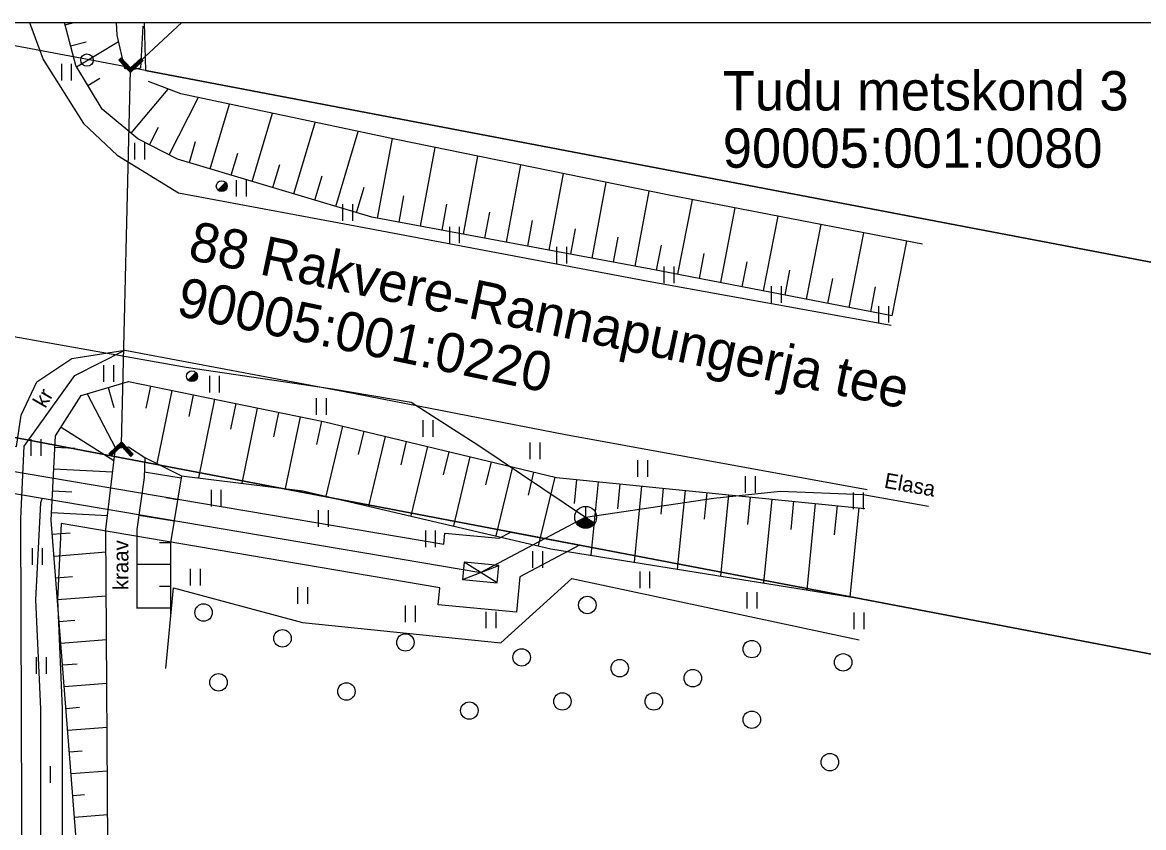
# Model space of a CAD drawing. Extents: x 657488 to 657645, y 6569018 to 6569240.
# Drawn here: x 657566.2 to 657617.6, y 6569166 to 6569202.9 of the extents above; entities that cross this region are included whole.
import ezdxf

# ---------------------------------------------------------------- set-up
doc = ezdxf.new("R2010")
doc.units = 0
for name, color, linetype in [('HALJASTUS', 7, 'Continuous'), ('KASUTUSALA', 7, 'Continuous'), ('PIIR', 7, 'Continuous'), ('PIIRIMLEITUD', 7, 'Continuous'), ('POST', 7, 'Continuous'), ('PR_SIDE', 7, 'Continuous'), ('RELJEEF', 7, 'Continuous'), ('SIKAEV', 7, 'Continuous'), ('SITRASS', 7, 'Continuous'), ('TEE', 7, 'Continuous'), ('TRUUP', 7, 'Continuous'), ('VEEKOGU', 7, 'Continuous'), ('VORMISTUS', 7, 'Continuous')]:
    doc.layers.add(name, color=color, linetype=linetype)

msp = doc.modelspace()

# ---------------------------------------------------------------- linework, layer by layer
at = {"layer": 'HALJASTUS'}
for p, q in [((657567.968, 6569200.963), (657567.968, 6569200.201)), ((657568.423, 6569200.963), (657568.423, 6569200.201)), ((657571.325, 6569197.337), (657571.325, 6569196.576)), ((657571.78, 6569197.337), (657571.78, 6569196.576)), ((657575.983, 6569195.634), (657575.983, 6569194.873)), ((657576.438, 6569195.634), (657576.438, 6569194.873)), ((657580.858, 6569194.531), (657580.858, 6569193.769)), ((657581.313, 6569194.531), (657581.313, 6569193.769)), ((657585.75, 6569193.495), (657585.75, 6569192.734)), ((657586.205, 6569193.495), (657586.205, 6569192.734)), ((657590.665, 6569192.576), (657590.665, 6569191.815)), ((657591.12, 6569192.576), (657591.12, 6569191.815)), ((657595.582, 6569191.67), (657595.582, 6569190.909)), ((657596.037, 6569191.67), (657596.037, 6569190.909)), ((657600.499, 6569190.765), (657600.499, 6569190.003)), ((657600.954, 6569190.765), (657600.954, 6569190.003)), ((657605.416, 6569189.859), (657605.416, 6569189.098)), ((657605.871, 6569189.859), (657605.871, 6569189.098)), ((657569.902, 6569187.152), (657569.902, 6569186.391)), ((657570.357, 6569187.152), (657570.357, 6569186.391)), ((657574.749, 6569186.655), (657574.749, 6569185.894)), ((657575.204, 6569186.655), (657575.204, 6569185.894)), ((657579.644, 6569185.638), (657579.644, 6569184.877)), ((657580.099, 6569185.638), (657580.099, 6569184.877)), ((657584.54, 6569184.621), (657584.54, 6569183.859)), ((657584.995, 6569184.621), (657584.995, 6569183.859)), ((657566.567, 6569183.759), (657566.567, 6569182.998)), ((657567.022, 6569183.759), (657567.022, 6569182.998)), ((657589.435, 6569183.604), (657589.435, 6569182.842)), ((657589.89, 6569183.604), (657589.89, 6569182.842)), ((657594.368, 6569182.796), (657594.368, 6569182.035)), ((657594.823, 6569182.796), (657594.823, 6569182.035)), ((657599.313, 6569182.056), (657599.313, 6569181.295)), ((657599.768, 6569182.056), (657599.768, 6569181.295)), ((657574.825, 6569181.436), (657574.825, 6569180.675)), ((657575.28, 6569181.436), (657575.28, 6569180.675)), ((657604.258, 6569181.316), (657604.258, 6569180.555)), ((657604.713, 6569181.316), (657604.713, 6569180.555)), ((657579.737, 6569180.5), (657579.737, 6569179.739)), ((657580.192, 6569180.5), (657580.192, 6569179.739)), ((657584.648, 6569179.564), (657584.648, 6569178.803)), ((657585.104, 6569179.564), (657585.104, 6569178.803)), ((657566.63, 6569178.761), (657566.63, 6569177.999)), ((657567.085, 6569178.761), (657567.085, 6569177.999)), ((657589.56, 6569178.628), (657589.56, 6569177.867)), ((657590.015, 6569178.628), (657590.015, 6569177.867)), ((657573.868, 6569177.812), (657573.868, 6569177.051)), ((657574.323, 6569177.812), (657574.323, 6569177.051)), ((657594.471, 6569177.69), (657594.471, 6569176.928)), ((657594.926, 6569177.69), (657594.926, 6569176.928)), ((657578.796, 6569176.97), (657578.796, 6569176.209)), ((657579.251, 6569176.97), (657579.251, 6569176.209)), ((657599.382, 6569176.751), (657599.382, 6569175.99)), ((657599.837, 6569176.751), (657599.837, 6569175.99)), ((657583.725, 6569176.127), (657583.725, 6569175.366)), ((657584.18, 6569176.127), (657584.18, 6569175.366)), ((657587.428, 6569175.85), (657587.428, 6569175.089)), ((657587.883, 6569175.85), (657587.883, 6569175.089)), ((657604.293, 6569175.812), (657604.293, 6569175.051)), ((657604.748, 6569175.812), (657604.748, 6569175.051)), ((657566.818, 6569173.764), (657566.818, 6569173.003)), ((657567.273, 6569173.764), (657567.273, 6569173.003)), ((657567.006, 6569168.768), (657567.006, 6569168.007)), ((657567.461, 6569168.768), (657567.461, 6569168.007))]:
    msp.add_line(p, q, dxfattribs=at)
msp.add_lwpolyline([(657572.749, 6569173.24), (657573.113, 6569176.938), (657579.023, 6569175.362), (657588.106, 6569174.428), (657591.366, 6569177.373), (657604.523, 6569174.557)], dxfattribs=at)
for centre in [(657592.072, 6569176.155), (657574.484, 6569175.812), (657578.1, 6569174.631), (657583.735, 6569174.441), (657599.61, 6569174.136), (657589.064, 6569173.755), (657603.797, 6569173.527), (657593.557, 6569173.26), (657596.907, 6569172.803), (657575.169, 6569172.613), (657581.032, 6569172.194), (657586.666, 6569171.318), (657590.93, 6569171.737), (657595.118, 6569171.737), (657599.61, 6569170.899), (657603.188, 6569168.956)]:
    msp.add_circle(centre, 0.4, dxfattribs=at)
at = {"layer": 'KASUTUSALA'}
msp.add_lwpolyline([(657547.908, 6569185.316), (657566.447, 6569182.172), (657567.352, 6569182.019), (657585.5, 6569178.941), (657585.549, 6569179.455), (657588.033, 6569179.219), (657588.559, 6569179.496), (657591.709, 6569178.895), (657588.975, 6569177.455), (657588.82, 6569175.829), (657585.236, 6569176.17), (657585.31, 6569176.945), (657567.959, 6569179.887), (657567.787, 6569176.392), (657568.004, 6569171.419), (657568.004, 6569151.046), (657568.454, 6569143.738), (657568.454, 6569131.107), (657569.487, 6569109.777)], dxfattribs=at)
at = {"layer": 'PIIR'}
for p, q in [((657628.561, 6569171.87), (657504.811, 6569195.461)), ((657504.811, 6569195.461), (657628.561, 6569171.87))]:
    msp.add_line(p, q, dxfattribs=at)
for points in [[(657628.561, 6569189.835), (657571.83, 6569200.65), (657569.16, 6569201.16), (657560.132, 6569202.856)], [(657571.761, 6569202.856), (657571.83, 6569200.65), (657569.16, 6569201.16), (657560.132, 6569202.856)], [(657571.761, 6569202.856), (657571.83, 6569200.65), (657628.561, 6569189.835)]]:
    msp.add_lwpolyline(points, dxfattribs=at)
at = {"layer": 'PIIRIMLEITUD'}
msp.add_circle((657569.14, 6569201.13), 0.285, dxfattribs=at)
at = {"layer": 'POST'}
for p, q in [((657575.14, 6569195.174), (657575.494, 6569195.527)), ((657573.777, 6569186.466), (657574.131, 6569186.819))]:
    msp.add_line(p, q, dxfattribs=at)
for centre in [(657575.317, 6569195.351), (657573.954, 6569186.643)]:
    msp.add_circle(centre, 0.25, dxfattribs=at)
for centre, radius, start, end in [((657575.317, 6569195.351), 0.225, 224.8541, 45.0356), ((657575.317, 6569195.351), 0.2, 224.8427, 45.047), ((657575.317, 6569195.351), 0.175, 224.8281, 45.0616), ((657575.317, 6569195.351), 0.15, 224.8087, 45.081), ((657575.317, 6569195.351), 0.125, 224.7814, 45.1083), ((657575.317, 6569195.351), 0.1, 224.7406, 45.1491), ((657575.317, 6569195.351), 0.075, 224.6725, 45.2172), ((657575.317, 6569195.351), 0.05, 224.5363, 45.3534), ((657575.317, 6569195.351), 0.025, 224.1278, 45.7619), ((657573.954, 6569186.643), 0.225, 224.8541, 45.0356), ((657573.954, 6569186.643), 0.2, 224.8427, 45.047), ((657573.954, 6569186.643), 0.175, 224.8281, 45.0616), ((657573.954, 6569186.643), 0.15, 224.8087, 45.081), ((657573.954, 6569186.643), 0.125, 224.7814, 45.1083), ((657573.954, 6569186.643), 0.1, 224.7406, 45.1491), ((657573.954, 6569186.643), 0.075, 224.6725, 45.2172), ((657573.954, 6569186.643), 0.05, 224.5363, 45.3534), ((657573.954, 6569186.643), 0.025, 224.1278, 45.7619)]:
    msp.add_arc(centre, radius, start, end, dxfattribs=at)
at = {"layer": 'PR_SIDE'}
for p, q in [((657586.35, 6569177.32), (657588.019, 6569177.964)), ((657587.943, 6569177.168), (657586.426, 6569178.116))]:
    msp.add_line(p, q, dxfattribs=at)
for points in [[(657549.982, 6569202.856), (657546.499, 6569184.945), (657546.67, 6569184.564), (657547.718, 6569184.335), (657567.085, 6569181.05), (657587.185, 6569177.642)], [(657567.085, 6569181.05), (657567.005, 6569180.843), (657566.787, 6569176.395), (657567.005, 6569171.398), (657567.005, 6569165.539), (657567.005, 6569158.584), (657567.005, 6569151.016), (657567.455, 6569143.708), (657567.455, 6569137.243), (657567.455, 6569131.084), (657568.489, 6569109.732), (657569.149, 6569094.452), (657569.149, 6569081.665), (657569.531, 6569068.343), (657563.3, 6569056.17)], [(657591.994, 6569180.175), (657587.185, 6569177.642)]]:
    msp.add_lwpolyline(points, dxfattribs=at)
msp.add_lwpolyline([(657586.35, 6569177.32), (657587.943, 6569177.168), (657588.019, 6569177.964), (657586.426, 6569178.116)], close=True, dxfattribs=at)
at = {"layer": 'RELJEEF'}
for p, q in [((657568.134, 6569202.75), (657568.532, 6569202.856)), ((657568.392, 6569201.783), (657569.101, 6569201.973)), ((657568.667, 6569200.824), (657570.587, 6569201.989)), ((657569.185, 6569199.969), (657569.733, 6569200.301)), ((657571.172, 6569197.775), (657572.86, 6569199.798)), ((657572.905, 6569196.791), (657574.243, 6569199.406)), ((657574.792, 6569196.145), (657575.677, 6569199.104)), ((657576.707, 6569195.572), (657577.641, 6569198.69)), ((657572.014, 6569197.247), (657572.425, 6569198.048)), ((657578.623, 6569194.998), (657579.605, 6569198.276)), ((657580.539, 6569194.424), (657581.569, 6569197.862)), ((657573.834, 6569196.432), (657574.121, 6569197.392)), ((657582.462, 6569193.878), (657583.14, 6569197.53)), ((657575.749, 6569195.858), (657576.053, 6569196.871)), ((657584.428, 6569193.513), (657585.1, 6569197.129)), ((657577.665, 6569195.285), (657577.985, 6569196.351)), ((657586.395, 6569193.148), (657587.059, 6569196.728)), ((657588.361, 6569192.783), (657589.019, 6569196.327)), ((657579.581, 6569194.711), (657579.917, 6569195.83)), ((657590.328, 6569192.418), (657590.979, 6569195.927)), ((657581.497, 6569194.137), (657581.848, 6569195.31)), ((657592.294, 6569192.053), (657592.939, 6569195.526)), ((657583.445, 6569193.696), (657583.67, 6569194.907)), ((657594.26, 6569191.688), (657594.899, 6569195.125)), ((657585.412, 6569193.331), (657585.634, 6569194.53)), ((657596.225, 6569191.312), (657596.89, 6569194.731)), ((657598.188, 6569190.93), (657598.854, 6569194.352)), ((657587.378, 6569192.966), (657587.598, 6569194.153)), ((657589.344, 6569192.601), (657589.563, 6569193.776)), ((657600.151, 6569190.548), (657600.818, 6569193.974)), ((657591.311, 6569192.236), (657591.527, 6569193.399)), ((657602.114, 6569190.166), (657602.781, 6569193.595)), ((657593.277, 6569191.871), (657593.491, 6569193.022)), ((657604.078, 6569189.785), (657604.745, 6569193.217)), ((657606.041, 6569189.403), (657606.709, 6569192.838)), ((657595.243, 6569191.503), (657595.465, 6569192.642)), ((657597.206, 6569191.121), (657597.428, 6569192.261)), ((657599.17, 6569190.739), (657599.392, 6569191.881)), ((657601.133, 6569190.357), (657601.355, 6569191.5)), ((657603.096, 6569189.975), (657603.318, 6569191.119)), ((657605.059, 6569189.594), (657605.282, 6569190.738)), ((657570.109, 6569186.122), (657570.374, 6569185.213)), ((657572.049, 6569186.19), (657571.841, 6569185.179)), ((657569.149, 6569185.842), (657570.443, 6569183.339)), ((657573.028, 6569185.989), (657572.341, 6569182.643)), ((657574.008, 6569185.788), (657573.805, 6569184.798)), ((657574.987, 6569185.587), (657574.248, 6569181.987)), ((657575.967, 6569185.386), (657575.726, 6569184.212)), ((657576.947, 6569185.185), (657576.24, 6569181.741)), ((657577.926, 6569184.984), (657577.696, 6569183.862)), ((657578.906, 6569184.783), (657578.231, 6569181.495)), ((657579.885, 6569184.581), (657579.664, 6569183.505)), ((657567.956, 6569184.314), (657570.376, 6569182.773)), ((657580.858, 6569184.351), (657580.089, 6569181.149)), ((657581.831, 6569184.118), (657581.575, 6569183.052)), ((657582.803, 6569183.884), (657582.037, 6569180.692)), ((657583.775, 6569183.65), (657583.52, 6569182.588)), ((657567.67, 6569183.39), (657568.591, 6569183.344)), ((657584.748, 6569183.417), (657583.984, 6569180.236)), ((657585.72, 6569183.183), (657585.466, 6569182.125)), ((657586.692, 6569182.95), (657585.931, 6569179.78)), ((657571.785, 6569182.918), (657571.785, 6569182.918)), ((657587.665, 6569182.716), (657587.411, 6569181.661)), ((657588.637, 6569182.483), (657587.878, 6569179.323)), ((657567.62, 6569182.391), (657570.316, 6569182.256)), ((657573.456, 6569181.969), (657571.766, 6569182.243)), ((657589.61, 6569182.249), (657589.357, 6569181.198)), ((657590.582, 6569182.016), (657589.826, 6569178.867)), ((657591.575, 6569181.907), (657591.465, 6569180.803)), ((657592.57, 6569181.807), (657592.234, 6569178.438)), ((657593.565, 6569181.708), (657593.451, 6569180.565)), ((657594.56, 6569181.608), (657594.212, 6569178.12)), ((657595.555, 6569181.509), (657595.437, 6569180.326)), ((657596.551, 6569181.41), (657596.19, 6569177.802)), ((657567.57, 6569181.392), (657568.446, 6569181.348)), ((657573.296, 6569180.982), (657572.749, 6569181.07)), ((657597.546, 6569181.31), (657597.423, 6569180.088)), ((657598.541, 6569181.211), (657598.168, 6569177.484)), ((657599.536, 6569181.111), (657599.41, 6569179.849)), ((657600.531, 6569181.012), (657600.147, 6569177.167)), ((657601.526, 6569180.913), (657601.396, 6569179.611)), ((657567.52, 6569180.394), (657570.084, 6569180.265)), ((657602.521, 6569180.813), (657602.125, 6569176.849)), ((657603.516, 6569180.714), (657603.382, 6569179.373)), ((657604.511, 6569180.614), (657604.103, 6569176.531)), ((657573.136, 6569179.994), (657571.517, 6569180.257)), ((657567.553, 6569179.396), (657568.372, 6569179.46)), ((657572.976, 6569179.007), (657572.459, 6569179.007)), ((657567.632, 6569178.399), (657570.014, 6569178.586)), ((657572.976, 6569178.007), (657571.427, 6569178.007)), ((657567.71, 6569177.402), (657568.48, 6569177.463)), ((657572.976, 6569177.007), (657572.459, 6569177.007)), ((657567.788, 6569176.405), (657570.026, 6569176.581)), ((657572.976, 6569176.007), (657571.427, 6569176.007)), ((657567.867, 6569175.408), (657568.588, 6569175.465)), ((657567.945, 6569174.411), (657570.038, 6569174.576)), ((657568.023, 6569173.415), (657568.697, 6569173.467)), ((657568.101, 6569172.418), (657570.05, 6569172.571)), ((657568.18, 6569171.421), (657568.805, 6569171.47)), ((657568.258, 6569170.424), (657570.061, 6569170.565)), ((657568.336, 6569169.427), (657568.913, 6569169.472)), ((657568.415, 6569168.43), (657570.073, 6569168.56)), ((657568.493, 6569167.433), (657569.022, 6569167.474)), ((657568.571, 6569166.436), (657570.085, 6569166.555))]:
    msp.add_line(p, q, dxfattribs=at)
for points in [[(657606.041, 6569189.403), (657594.981, 6569191.554), (657582.198, 6569193.928), (657573.286, 6569196.596), (657571.475, 6569197.523), (657569.843, 6569198.884), (657568.634, 6569200.878), (657568.106, 6569202.856)], [(657607.435, 6569192.698), (657595.829, 6569194.935), (657583.316, 6569197.493), (657573.437, 6569199.576), (657571.955, 6569200.147)], [(657575.356, 6569071.541), (657575.057, 6569070.915), (657574.198, 6569070.482), (657573.247, 6569070.288), (657571.97, 6569070.573), (657571.429, 6569071.459), (657570.978, 6569085.148), (657570.566, 6569100.675), (657570.041, 6569122.388), (657569.282, 6569141.747), (657568.88, 6569162.504), (657567.502, 6569180.047), (657567.696, 6569183.905), (657568.878, 6569185.763), (657571.048, 6569186.396), (657579.979, 6569184.562), (657590.654, 6569181.999), (657604.789, 6569180.587)], [(657571.785, 6569182.918), (657573.475, 6569182.082), (657572.976, 6569179.009), (657572.976, 6569175.684)], [(657573.475, 6569182.082), (657579.032, 6569181.396), (657590.406, 6569178.731), (657604.194, 6569176.517)]]:
    msp.add_lwpolyline(points, dxfattribs=at)
at = {"layer": 'SIKAEV'}
for p, q in [((657591.994, 6569180.675), (657591.994, 6569180.175)), ((657591.994, 6569180.175), (657591.579, 6569179.9)), ((657591.994, 6569180.175), (657592.409, 6569179.9))]:
    msp.add_line(p, q, dxfattribs=at)
msp.add_circle((657591.994, 6569180.175), 0.5, dxfattribs=at)
for radius in [0.475, 0.45, 0.425, 0.4, 0.375, 0.35, 0.325, 0.3, 0.275, 0.25, 0.225, 0.2, 0.175, 0.15, 0.125, 0.1, 0.075, 0.05]:
    msp.add_arc((657591.994, 6569180.175), radius, 213.5305, 326.4695, dxfattribs=at)
at = {"layer": 'SITRASS'}
for points in [[(657538.526, 6569193.931), (657544.74, 6569192.801), (657554.786, 6569190.635), (657557.448, 6569189.839), (657560.207, 6569189.461), (657567.755, 6569188.116), (657573.682, 6569187.05), (657580.3, 6569186.079), (657583.994, 6569185.454)], [(657538.53, 6569193.962), (657540.073, 6569193.683), (657548.471, 6569192.073), (657554.786, 6569190.635), (657557.448, 6569189.839), (657560.207, 6569189.461), (657567.755, 6569188.116), (657573.682, 6569187.05), (657580.3, 6569186.079), (657583.994, 6569185.454), (657587.105, 6569183.47), (657591.994, 6569180.175)], [(657591.994, 6569180.175), (657597.864, 6569181.06), (657600.917, 6569181.376), (657604.715, 6569181.224), (657607.706, 6569180.682)]]:
    msp.add_lwpolyline(points, dxfattribs=at)
at = {"layer": 'TEE'}
for points in [[(657566.514, 6569202.856), (657567.13, 6569201.162), (657568.979, 6569198.218), (657570.531, 6569196.773), (657573.339, 6569195.045), (657582.093, 6569193.414), (657594.865, 6569191), (657606.002, 6569188.987)], [(657539.768, 6569193.688), (657544.74, 6569192.801), (657558.334, 6569190.212), (657560.446, 6569189.13), (657561.615, 6569187.822), (657562.318, 6569185.969), (657562.357, 6569183.895), (657565.907, 6569183.428), (657566.128, 6569184.861), (657566.85, 6569186.392), (657568.446, 6569187.459), (657570.879, 6569187.829), (657580.948, 6569185.939), (657591.065, 6569183.973), (657604.904, 6569181.447)], [(657554.399, 6569061.998), (657559.246, 6569063.029), (657564.816, 6569064.832), (657569.624, 6569065.374), (657570.355, 6569067.363), (657568.529, 6569067.262), (657568.594, 6569069.383), (657568.421, 6569074.299), (657568.495, 6569085.242), (657567.806, 6569100.86), (657567.283, 6569122.208), (657566.728, 6569141.772), (657566.168, 6569162.215), (657566.107, 6569180.122), (657566.259, 6569183.437), (657568.587, 6569186.681), (657570.879, 6569187.829)]]:
    msp.add_lwpolyline(points, dxfattribs=at)
at = {"layer": 'TRUUP'}
for p, q in [((657571.141, 6569200.667), (657573.49, 6569202.856)), ((657570.705, 6569201.228), (657570.601, 6569201.13)), ((657570.601, 6569201.13), (657571.138, 6569200.567)), ((657570.623, 6569201.151), (657570.642, 6569201.088)), ((657570.643, 6569201.17), (657570.68, 6569201.048)), ((657570.653, 6569201.179), (657571.141, 6569200.667)), ((657570.663, 6569201.189), (657570.718, 6569201.008)), ((657570.684, 6569201.208), (657570.757, 6569200.967)), ((657570.704, 6569201.228), (657570.795, 6569200.927)), ((657570.705, 6569201.228), (657571.143, 6569200.768)), ((657570.742, 6569201.19), (657570.833, 6569200.887)), ((657570.78, 6569201.149), (657570.872, 6569200.847)), ((657570.818, 6569201.109), (657570.91, 6569200.806)), ((657570.856, 6569201.069), (657570.948, 6569200.766)), ((657570.895, 6569201.029), (657570.986, 6569200.726)), ((657570.933, 6569200.988), (657571.025, 6569200.686)), ((657570.971, 6569200.948), (657571.063, 6569200.645)), ((657571.138, 6569200.567), (657571.702, 6569201.103)), ((657571.141, 6569200.667), (657571.653, 6569201.155)), ((657571.143, 6569200.768), (657571.604, 6569201.206)), ((657571.316, 6569200.932), (657571.362, 6569200.78)), ((657571.336, 6569200.952), (657571.382, 6569200.799)), ((657571.356, 6569200.971), (657571.403, 6569200.818)), ((657571.377, 6569200.99), (657571.423, 6569200.838)), ((657571.397, 6569201.009), (657571.443, 6569200.857)), ((657571.417, 6569201.029), (657571.463, 6569200.876)), ((657571.437, 6569201.048), (657571.484, 6569200.895)), ((657571.458, 6569201.067), (657571.504, 6569200.915)), ((657571.478, 6569201.087), (657571.524, 6569200.934)), ((657571.498, 6569201.106), (657571.544, 6569200.953)), ((657571.519, 6569201.125), (657571.565, 6569200.973)), ((657571.539, 6569201.145), (657571.585, 6569200.992)), ((657571.559, 6569201.164), (657571.605, 6569201.011)), ((657571.579, 6569201.183), (657571.626, 6569201.031)), ((657571.6, 6569201.202), (657571.646, 6569201.05)), ((657571.604, 6569201.206), (657571.702, 6569201.103)), ((657571.634, 6569201.174), (657571.666, 6569201.069)), ((657571.673, 6569201.134), (657571.686, 6569201.089)), ((657571.01, 6569200.908), (657571.101, 6569200.605)), ((657571.048, 6569200.868), (657571.139, 6569200.567)), ((657571.086, 6569200.827), (657571.159, 6569200.587)), ((657571.125, 6569200.787), (657571.179, 6569200.606)), ((657571.154, 6569200.778), (657571.2, 6569200.625)), ((657571.174, 6569200.797), (657571.22, 6569200.645)), ((657571.194, 6569200.816), (657571.24, 6569200.664)), ((657571.214, 6569200.836), (657571.261, 6569200.683)), ((657571.235, 6569200.855), (657571.281, 6569200.702)), ((657571.255, 6569200.874), (657571.301, 6569200.722)), ((657571.275, 6569200.894), (657571.321, 6569200.741)), ((657571.295, 6569200.913), (657571.342, 6569200.76)), ((657570.721, 6569183.63), (657570.158, 6569183.093)), ((657570.719, 6569183.529), (657570.207, 6569183.042)), ((657570.605, 6569183.322), (657570.558, 6569183.475)), ((657570.625, 6569183.342), (657570.579, 6569183.494)), ((657570.645, 6569183.361), (657570.599, 6569183.513)), ((657570.665, 6569183.38), (657570.619, 6569183.533)), ((657570.686, 6569183.399), (657570.64, 6569183.552)), ((657570.706, 6569183.419), (657570.66, 6569183.571)), ((657570.735, 6569183.409), (657570.68, 6569183.591)), ((657570.773, 6569183.369), (657570.7, 6569183.61)), ((657571.207, 6569183.017), (657570.719, 6569183.529)), ((657571.258, 6569183.066), (657570.721, 6569183.63)), ((657570.812, 6569183.329), (657570.721, 6569183.629)), ((657570.85, 6569183.289), (657570.758, 6569183.591)), ((657570.888, 6569183.248), (657570.797, 6569183.551)), ((657570.927, 6569183.208), (657570.835, 6569183.511)), ((657570.965, 6569183.168), (657570.873, 6569183.471)), ((657570.256, 6569182.99), (657570.158, 6569183.093)), ((657570.187, 6569183.063), (657570.173, 6569183.108)), ((657570.225, 6569183.023), (657570.193, 6569183.127)), ((657570.26, 6569182.994), (657570.214, 6569183.147)), ((657570.28, 6569183.013), (657570.234, 6569183.166)), ((657570.301, 6569183.033), (657570.254, 6569183.185)), ((657570.717, 6569183.429), (657570.256, 6569182.99)), ((657570.321, 6569183.052), (657570.275, 6569183.205)), ((657570.341, 6569183.071), (657570.295, 6569183.224)), ((657570.361, 6569183.091), (657570.315, 6569183.243)), ((657570.382, 6569183.11), (657570.335, 6569183.263)), ((657570.402, 6569183.129), (657570.356, 6569183.282)), ((657570.422, 6569183.149), (657570.376, 6569183.301)), ((657570.442, 6569183.168), (657570.396, 6569183.32)), ((657570.463, 6569183.187), (657570.417, 6569183.34)), ((657570.483, 6569183.206), (657570.437, 6569183.359)), ((657570.503, 6569183.226), (657570.457, 6569183.378)), ((657570.524, 6569183.245), (657570.477, 6569183.398)), ((657570.544, 6569183.264), (657570.498, 6569183.417)), ((657570.564, 6569183.284), (657570.518, 6569183.436)), ((657570.584, 6569183.303), (657570.538, 6569183.456)), ((657571.155, 6569182.968), (657570.717, 6569183.429)), ((657571.003, 6569183.128), (657570.911, 6569183.43)), ((657571.041, 6569183.087), (657570.95, 6569183.39)), ((657571.08, 6569183.047), (657570.988, 6569183.35)), ((657571.118, 6569183.007), (657571.026, 6569183.31)), ((657571.156, 6569182.969), (657571.065, 6569183.27)), ((657571.176, 6569182.988), (657571.103, 6569183.229)), ((657571.196, 6569183.007), (657571.141, 6569183.189)), ((657571.155, 6569182.968), (657571.258, 6569183.066)), ((657571.217, 6569183.027), (657571.18, 6569183.149)), ((657571.237, 6569183.046), (657571.218, 6569183.109))]:
    msp.add_line(p, q, dxfattribs=at)
msp.add_lwpolyline([(657570.719, 6569183.529), (657571.141, 6569200.667)], dxfattribs=at)
at = {"layer": 'VEEKOGU'}
for points in [[(657571.695, 6569202.687), (657571.595, 6569200.762), (657571.141, 6569200.667), (657570.88, 6569200.75), (657570.52, 6569202.271), (657570.5, 6569202.856)], [(657574.071, 6569073.057), (657573.984, 6569072.504), (657573.232, 6569071.885), (657573.039, 6569072.48), (657572.681, 6569085.311), (657572.365, 6569101.179), (657572.042, 6569122.585), (657571.255, 6569141.933), (657570.107, 6569162.81), (657570.008, 6569179.615), (657570.443, 6569183.339), (657571.044, 6569183.413), (657571.785, 6569182.918), (657571.76, 6569181.994), (657571.427, 6569179.615), (657571.427, 6569175.989)]]:
    msp.add_lwpolyline(points, dxfattribs=at)
at = {"layer": 'VORMISTUS'}
msp.add_lwpolyline([(657628.561, 6569045.356), (657504.811, 6569045.356), (657504.811, 6569202.856), (657628.561, 6569202.856)], close=True, dxfattribs=at)

# ---------------------------------------------------------------- texts
at = {"layer": 'PIIR'}
for s, p in [('Tudu metskond 3', (657598.28, 6569198.822)), ('90005:001:0080', (657598.28, 6569196.197))]:
    msp.add_text(s, height=1.8, dxfattribs=at).set_placement(p)
for s, p in [('88 Rakvere-Rannapungerja tee', (657573.715, 6569192.008)), ('90005:001:0220', (657573.179, 6569189.439))]:
    msp.add_text(s, height=1.8, rotation=348.2069, dxfattribs=at).set_placement(p)
at = {"layer": 'SITRASS'}
msp.add_text('Elasa', height=0.7, rotation=349.6902, dxfattribs=at).set_placement((657605.644, 6569181.537))
at = {"layer": 'TEE'}
msp.add_text('kr', height=0.7, rotation=59.7552, dxfattribs=at).set_placement((657567.231, 6569185.138))
at = {"layer": 'VEEKOGU'}
msp.add_text('kraav', height=0.7, rotation=89.9544, dxfattribs=at).set_placement((657571.039, 6569176.837))

doc.saveas('drawing.dxf')
